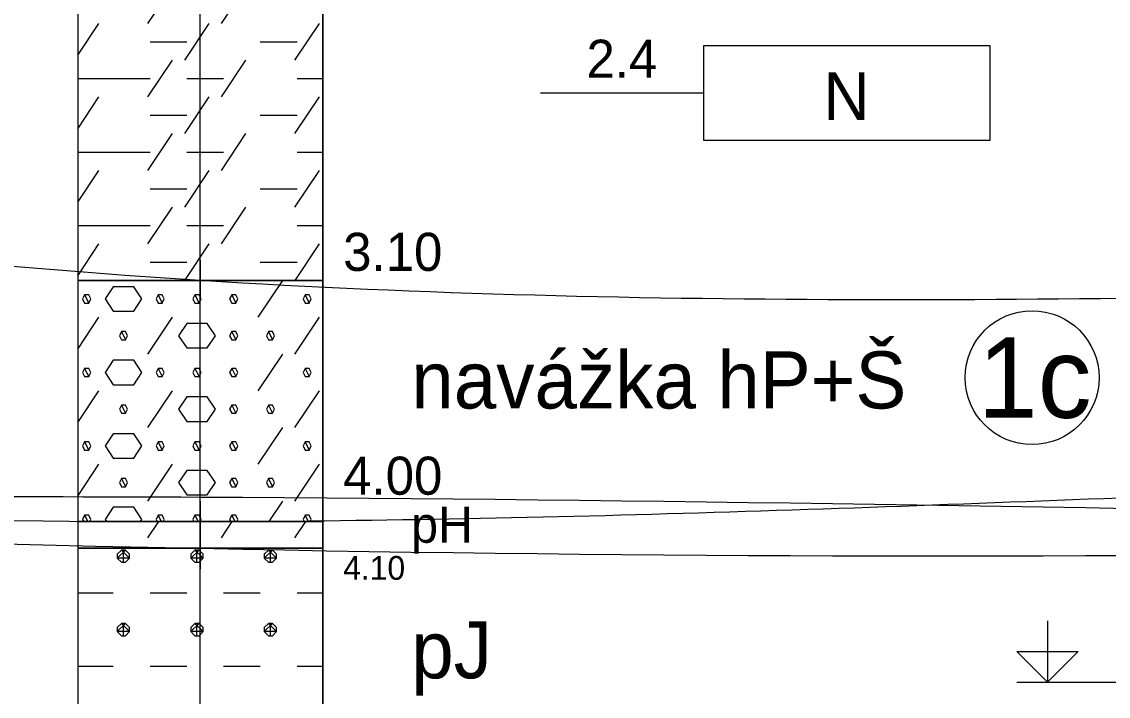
# Model space of a CAD drawing. Extents: x 3042 to 4120, y 576 to 2694.
# Drawn here: x 3328.17 to 3348.45, y 1428.2 to 1440.79 of the extents above; entities that cross this region are included whole.
import ezdxf

# ---------------------------------------------------------------- set-up
doc = ezdxf.new("R2010")
doc.units = 0
for name, color, linetype in [('18', 7, 'Continuous'), ('51', 7, 'Continuous'), ('52', 7, 'Continuous'), ('53', 7, 'Continuous'), ('56', 7, 'Continuous'), ('61', 7, 'Continuous'), ('62', 7, 'Continuous'), ('HPV', 7, 'Continuous'), ('rozhraní', 7, 'Continuous')]:
    doc.layers.add(name, color=color, linetype=linetype)

msp = doc.modelspace()

# ---------------------------------------------------------------- linework, layer by layer
at = {"layer": '18'}
msp.add_line((3331.502, 1401.464), (3331.502, 1451.464), dxfattribs=at)
at = {"layer": '51'}
for p, q in [((3330.526, 1440.762), (3330.984, 1441.448)), ((3331.898, 1440.762), (3332.355, 1441.448)), ((3329.216, 1440.168), (3329.612, 1440.762)), ((3331.212, 1440.076), (3331.669, 1440.762)), ((3333.27, 1440.076), (3333.727, 1440.762)), ((3330.565, 1440.419), (3331.25, 1440.419)), ((3332.622, 1440.419), (3333.308, 1440.419)), ((3330.526, 1439.39), (3330.984, 1440.076)), ((3331.898, 1439.39), (3332.355, 1440.076)), ((3329.216, 1439.733), (3329.879, 1439.733)), ((3329.879, 1439.733), (3330.565, 1439.733)), ((3331.25, 1439.733), (3331.936, 1439.733)), ((3333.308, 1439.733), (3333.788, 1439.733)), ((3329.216, 1438.796), (3329.612, 1439.39)), ((3331.212, 1438.705), (3331.669, 1439.39)), ((3333.27, 1438.705), (3333.727, 1439.39)), ((3330.565, 1439.048), (3331.25, 1439.048)), ((3332.622, 1439.048), (3333.308, 1439.048)), ((3330.526, 1438.019), (3330.984, 1438.705)), ((3331.898, 1438.019), (3332.355, 1438.705)), ((3329.216, 1438.362), (3329.879, 1438.362)), ((3329.879, 1438.362), (3330.565, 1438.362)), ((3331.25, 1438.362), (3331.936, 1438.362)), ((3333.308, 1438.362), (3333.788, 1438.362)), ((3329.216, 1437.424), (3329.612, 1438.019)), ((3331.212, 1437.333), (3331.669, 1438.019)), ((3333.27, 1437.333), (3333.727, 1438.019)), ((3330.565, 1437.676), (3331.25, 1437.676)), ((3332.622, 1437.676), (3333.308, 1437.676)), ((3330.526, 1436.647), (3330.984, 1437.333)), ((3331.898, 1436.647), (3332.355, 1437.333)), ((3329.216, 1436.99), (3329.879, 1436.99)), ((3329.879, 1436.99), (3330.565, 1436.99)), ((3331.25, 1436.99), (3331.936, 1436.99)), ((3333.308, 1436.99), (3333.788, 1436.99)), ((3329.216, 1436.053), (3329.612, 1436.647)), ((3331.214, 1435.964), (3331.669, 1436.647)), ((3333.271, 1435.964), (3333.727, 1436.647)), ((3330.565, 1436.304), (3331.25, 1436.304)), ((3332.622, 1436.304), (3333.308, 1436.304)), ((3330.526, 1435.961), (3330.528, 1435.964)), ((3332.584, 1435.276), (3333.041, 1435.961)), ((3333.27, 1435.961), (3333.271, 1435.964)), ((3329.216, 1434.681), (3329.612, 1435.276)), ((3330.526, 1434.59), (3330.984, 1435.276)), ((3333.27, 1434.59), (3333.727, 1435.276)), ((3332.584, 1433.904), (3333.041, 1434.59)), ((3329.216, 1433.31), (3329.612, 1433.904)), ((3330.526, 1433.218), (3330.984, 1433.904)), ((3333.27, 1433.218), (3333.727, 1433.904)), ((3332.584, 1432.532), (3333.041, 1433.218)), ((3329.216, 1431.938), (3329.612, 1432.532)), ((3330.526, 1431.847), (3330.984, 1432.532)), ((3333.27, 1431.847), (3333.727, 1432.532)), ((3332.786, 1431.464), (3333.041, 1431.847)), ((3330.526, 1431.161), (3330.728, 1431.464)), ((3331.898, 1431.161), (3332.1, 1431.464)), ((3333.27, 1431.161), (3333.472, 1431.464)), ((3330.069, 1430.704), (3330.069, 1430.932)), ((3331.441, 1430.704), (3331.441, 1430.932)), ((3332.812, 1430.704), (3332.812, 1430.932)), ((3329.216, 1430.132), (3329.879, 1430.132)), ((3330.565, 1430.132), (3331.25, 1430.132)), ((3331.936, 1430.132), (3332.622, 1430.132)), ((3333.308, 1430.132), (3333.788, 1430.132)), ((3330.069, 1429.332), (3330.069, 1429.561)), ((3331.441, 1429.332), (3331.441, 1429.561)), ((3332.812, 1429.332), (3332.812, 1429.561)), ((3329.216, 1428.761), (3329.879, 1428.761)), ((3330.565, 1428.761), (3331.25, 1428.761)), ((3331.936, 1428.761), (3332.622, 1428.761)), ((3333.308, 1428.761), (3333.788, 1428.761))]:
    msp.add_line(p, q, dxfattribs=at)
for points in [[(3329.216, 1435.964), (3333.788, 1435.964), (3333.788, 1445.464), (3329.216, 1445.464)], [(3329.216, 1431.464), (3333.788, 1431.464), (3333.788, 1435.964), (3329.216, 1435.964)], [(3329.216, 1430.964), (3333.788, 1430.964), (3333.788, 1431.464), (3329.216, 1431.464)], [(3329.216, 1427.464), (3333.788, 1427.464), (3333.788, 1430.964), (3329.216, 1430.964)]]:
    msp.add_lwpolyline(points, close=True, dxfattribs=at)
for points in [[(3329.879, 1435.39), (3330.26, 1435.39), (3330.412, 1435.619), (3330.26, 1435.847), (3329.879, 1435.847), (3329.726, 1435.619), (3329.879, 1435.39)], [(3329.345, 1435.695), (3329.307, 1435.619), (3329.345, 1435.542), (3329.422, 1435.542), (3329.46, 1435.619), (3329.422, 1435.695), (3329.345, 1435.695), (3329.422, 1435.542)], [(3330.717, 1435.695), (3330.679, 1435.619), (3330.717, 1435.542), (3330.793, 1435.542), (3330.831, 1435.619), (3330.793, 1435.695), (3330.717, 1435.695), (3330.793, 1435.542)], [(3331.403, 1435.695), (3331.365, 1435.619), (3331.403, 1435.542), (3331.479, 1435.542), (3331.517, 1435.619), (3331.479, 1435.695), (3331.403, 1435.695), (3331.479, 1435.542)], [(3332.089, 1435.695), (3332.05, 1435.619), (3332.089, 1435.542), (3332.165, 1435.542), (3332.203, 1435.619), (3332.165, 1435.695), (3332.089, 1435.695), (3332.165, 1435.542)], [(3333.46, 1435.695), (3333.422, 1435.619), (3333.46, 1435.542), (3333.536, 1435.542), (3333.574, 1435.619), (3333.536, 1435.695), (3333.46, 1435.695), (3333.536, 1435.542)], [(3331.25, 1434.704), (3331.631, 1434.704), (3331.784, 1434.933), (3331.631, 1435.161), (3331.25, 1435.161), (3331.098, 1434.933), (3331.25, 1434.704)], [(3330.031, 1435.009), (3329.993, 1434.933), (3330.031, 1434.857), (3330.107, 1434.857), (3330.145, 1434.933), (3330.107, 1435.009), (3330.031, 1435.009), (3330.107, 1434.857)], [(3332.089, 1435.009), (3332.05, 1434.933), (3332.089, 1434.857), (3332.165, 1434.857), (3332.203, 1434.933), (3332.165, 1435.009), (3332.089, 1435.009), (3332.165, 1434.857)], [(3332.774, 1435.009), (3332.736, 1434.933), (3332.774, 1434.857), (3332.851, 1434.857), (3332.889, 1434.933), (3332.851, 1435.009), (3332.774, 1435.009), (3332.851, 1434.857)], [(3329.879, 1434.018), (3330.26, 1434.018), (3330.412, 1434.247), (3330.26, 1434.476), (3329.879, 1434.476), (3329.726, 1434.247), (3329.879, 1434.018)], [(3329.345, 1434.323), (3329.307, 1434.247), (3329.345, 1434.171), (3329.422, 1434.171), (3329.46, 1434.247), (3329.422, 1434.323), (3329.345, 1434.323), (3329.422, 1434.171)], [(3330.717, 1434.323), (3330.679, 1434.247), (3330.717, 1434.171), (3330.793, 1434.171), (3330.831, 1434.247), (3330.793, 1434.323), (3330.717, 1434.323), (3330.793, 1434.171)], [(3331.403, 1434.323), (3331.365, 1434.247), (3331.403, 1434.171), (3331.479, 1434.171), (3331.517, 1434.247), (3331.479, 1434.323), (3331.403, 1434.323), (3331.479, 1434.171)], [(3332.089, 1434.323), (3332.05, 1434.247), (3332.089, 1434.171), (3332.165, 1434.171), (3332.203, 1434.247), (3332.165, 1434.323), (3332.089, 1434.323), (3332.165, 1434.171)], [(3333.46, 1434.323), (3333.422, 1434.247), (3333.46, 1434.171), (3333.536, 1434.171), (3333.574, 1434.247), (3333.536, 1434.323), (3333.46, 1434.323), (3333.536, 1434.171)], [(3330.031, 1433.637), (3329.993, 1433.561), (3330.031, 1433.485), (3330.107, 1433.485), (3330.145, 1433.561), (3330.107, 1433.637), (3330.031, 1433.637), (3330.107, 1433.485)], [(3331.25, 1433.333), (3331.631, 1433.333), (3331.784, 1433.561), (3331.631, 1433.79), (3331.25, 1433.79), (3331.098, 1433.561), (3331.25, 1433.333)], [(3332.089, 1433.637), (3332.05, 1433.561), (3332.089, 1433.485), (3332.165, 1433.485), (3332.203, 1433.561), (3332.165, 1433.637), (3332.089, 1433.637), (3332.165, 1433.485)], [(3332.774, 1433.637), (3332.736, 1433.561), (3332.774, 1433.485), (3332.851, 1433.485), (3332.889, 1433.561), (3332.851, 1433.637), (3332.774, 1433.637), (3332.851, 1433.485)], [(3329.879, 1432.647), (3330.26, 1432.647), (3330.412, 1432.875), (3330.26, 1433.104), (3329.879, 1433.104), (3329.726, 1432.875), (3329.879, 1432.647)], [(3329.345, 1432.952), (3329.307, 1432.875), (3329.345, 1432.799), (3329.422, 1432.799), (3329.46, 1432.875), (3329.422, 1432.952), (3329.345, 1432.952), (3329.422, 1432.799)], [(3330.717, 1432.952), (3330.679, 1432.875), (3330.717, 1432.799), (3330.793, 1432.799), (3330.831, 1432.875), (3330.793, 1432.952), (3330.717, 1432.952), (3330.793, 1432.799)], [(3331.403, 1432.952), (3331.365, 1432.875), (3331.403, 1432.799), (3331.479, 1432.799), (3331.517, 1432.875), (3331.479, 1432.952), (3331.403, 1432.952), (3331.479, 1432.799)], [(3332.089, 1432.952), (3332.05, 1432.875), (3332.089, 1432.799), (3332.165, 1432.799), (3332.203, 1432.875), (3332.165, 1432.952), (3332.089, 1432.952), (3332.165, 1432.799)], [(3333.46, 1432.952), (3333.422, 1432.875), (3333.46, 1432.799), (3333.536, 1432.799), (3333.574, 1432.875), (3333.536, 1432.952), (3333.46, 1432.952), (3333.536, 1432.799)], [(3331.25, 1431.961), (3331.631, 1431.961), (3331.784, 1432.19), (3331.631, 1432.418), (3331.25, 1432.418), (3331.098, 1432.19), (3331.25, 1431.961)], [(3330.031, 1432.266), (3329.993, 1432.19), (3330.031, 1432.113), (3330.107, 1432.113), (3330.145, 1432.19), (3330.107, 1432.266), (3330.031, 1432.266), (3330.107, 1432.113)], [(3332.089, 1432.266), (3332.05, 1432.19), (3332.089, 1432.113), (3332.165, 1432.113), (3332.203, 1432.19), (3332.165, 1432.266), (3332.089, 1432.266), (3332.165, 1432.113)], [(3332.774, 1432.266), (3332.736, 1432.19), (3332.774, 1432.113), (3332.851, 1432.113), (3332.889, 1432.19), (3332.851, 1432.266), (3332.774, 1432.266), (3332.851, 1432.113)], [(3329.345, 1431.58), (3329.307, 1431.504), (3329.327, 1431.464)], [(3329.44, 1431.464), (3329.46, 1431.504), (3329.422, 1431.58), (3329.345, 1431.58), (3329.403, 1431.464)], [(3330.386, 1431.464), (3330.412, 1431.504), (3330.26, 1431.732), (3329.879, 1431.732), (3329.726, 1431.504), (3329.753, 1431.464)], [(3330.717, 1431.58), (3330.679, 1431.504), (3330.699, 1431.464)], [(3330.811, 1431.464), (3330.831, 1431.504), (3330.793, 1431.58), (3330.717, 1431.58), (3330.775, 1431.464)], [(3331.403, 1431.58), (3331.365, 1431.504), (3331.385, 1431.464)], [(3331.497, 1431.464), (3331.517, 1431.504), (3331.479, 1431.58), (3331.403, 1431.58), (3331.461, 1431.464)], [(3332.089, 1431.58), (3332.05, 1431.504), (3332.07, 1431.464)], [(3332.183, 1431.464), (3332.203, 1431.504), (3332.165, 1431.58), (3332.089, 1431.58), (3332.147, 1431.464)], [(3333.46, 1431.58), (3333.422, 1431.504), (3333.442, 1431.464)], [(3333.554, 1431.464), (3333.574, 1431.504), (3333.536, 1431.58), (3333.46, 1431.58), (3333.518, 1431.464)], [(3330.031, 1430.932), (3329.955, 1430.856), (3329.955, 1430.78), (3330.031, 1430.704), (3330.107, 1430.704), (3330.184, 1430.78), (3330.184, 1430.856), (3330.107, 1430.932), (3330.031, 1430.932), (3330.184, 1430.78), (3329.955, 1430.78), (3330.107, 1430.932)], [(3331.403, 1430.932), (3331.327, 1430.856), (3331.327, 1430.78), (3331.403, 1430.704), (3331.479, 1430.704), (3331.555, 1430.78), (3331.555, 1430.856), (3331.479, 1430.932), (3331.403, 1430.932), (3331.555, 1430.78), (3331.327, 1430.78), (3331.479, 1430.932)], [(3332.774, 1430.932), (3332.698, 1430.856), (3332.698, 1430.78), (3332.774, 1430.704), (3332.851, 1430.704), (3332.927, 1430.78), (3332.927, 1430.856), (3332.851, 1430.932), (3332.774, 1430.932), (3332.927, 1430.78), (3332.698, 1430.78), (3332.851, 1430.932)], [(3330.031, 1429.561), (3329.955, 1429.484), (3329.955, 1429.408), (3330.031, 1429.332), (3330.107, 1429.332), (3330.184, 1429.408), (3330.184, 1429.484), (3330.107, 1429.561), (3330.031, 1429.561), (3330.184, 1429.408), (3329.955, 1429.408), (3330.107, 1429.561)], [(3331.403, 1429.561), (3331.327, 1429.484), (3331.327, 1429.408), (3331.403, 1429.332), (3331.479, 1429.332), (3331.555, 1429.408), (3331.555, 1429.484), (3331.479, 1429.561), (3331.403, 1429.561), (3331.555, 1429.408), (3331.327, 1429.408), (3331.479, 1429.561)], [(3332.774, 1429.561), (3332.698, 1429.484), (3332.698, 1429.408), (3332.774, 1429.332), (3332.851, 1429.332), (3332.927, 1429.408), (3332.927, 1429.484), (3332.851, 1429.561), (3332.774, 1429.561), (3332.927, 1429.408), (3332.698, 1429.408), (3332.851, 1429.561)]]:
    msp.add_lwpolyline(points, dxfattribs=at)
at = {"layer": '53'}
for p, q in [((3329.216, 1451.464), (3329.216, 1401.464)), ((3333.788, 1451.464), (3333.788, 1401.464)), ((3329.216, 1435.964), (3333.788, 1435.964)), ((3329.216, 1431.464), (3333.788, 1431.464)), ((3329.216, 1430.964), (3333.788, 1430.964))]:
    msp.add_line(p, q, dxfattribs=at)
at = {"layer": '56'}
for p, q in [((3331.502, 1436.345), (3331.502, 1435.583)), ((3331.121, 1435.964), (3331.883, 1435.964)), ((3331.502, 1431.845), (3331.502, 1431.083)), ((3331.121, 1431.464), (3331.883, 1431.464)), ((3331.502, 1431.345), (3331.502, 1430.583)), ((3331.121, 1430.964), (3331.883, 1430.964))]:
    msp.add_line(p, q, dxfattribs=at)
at = {"layer": '61'}
msp.add_line((3346.742, 1428.464), (3351.737, 1428.464), dxfattribs=at)
msp.add_lwpolyline([(3347.313, 1429.607), (3347.313, 1428.464), (3346.742, 1429.035), (3347.885, 1429.035), (3347.313, 1428.464)], dxfattribs=at)
at = {"layer": '62'}
msp.add_line((3337.852, 1439.464), (3340.9, 1439.464), dxfattribs=at)
msp.add_lwpolyline([(3346.234, 1438.575), (3340.9, 1438.575), (3340.9, 1440.353), (3346.234, 1440.353), (3346.234, 1438.575)], dxfattribs=at)
at = {"layer": 'HPV'}
msp.add_spline([(3456.273, 1433.82), (3381.832, 1431.271), (3331.502, 1431.914), (3319.823, 1431.914)], degree=3, dxfattribs=at)
at = {"layer": 'rozhraní'}
msp.add_circle((3347.024, 1434.15), 1.25, dxfattribs=at)
for points in [[(3356.525, 1435.755), (3331.502, 1435.964), (3301.662, 1439.299), (3286.47, 1440.682)], [(3260.637, 1433.124), (3269.032, 1433.064), (3331.502, 1430.964), (3381.832, 1431.714), (3448.222, 1434.864), (3457.804, 1434.864)], [(3260.628, 1434.017), (3269.032, 1434.064), (3331.497, 1431.464), (3350.107, 1431.964)], [(3261.496, 1419.657), (3269.032, 1420.064), (3276.869, 1420.657), (3284.683, 1421.527), (3300.27, 1423.734), (3315.855, 1425.956), (3323.667, 1426.844), (3331.502, 1427.464), (3344.075, 1427.667), (3356.665, 1427.215), (3369.255, 1426.701), (3381.832, 1426.714), (3398.427, 1427.714), (3415.014, 1429.102), (3431.607, 1430.333), (3448.222, 1430.864), (3456.64, 1430.864)]]:
    msp.add_spline(points, degree=3, dxfattribs=at)

# ---------------------------------------------------------------- texts
at = {"layer": '52'}
for s, height, p in [('3.10', 0.7112, (3334.169, 1436.143)), ('navážka hP+Š', 1.0668, (3335.439, 1433.574)), ('4.00', 0.7112, (3334.169, 1431.964)), ('pH', 0.6731, (3335.439, 1431.067)), ('4.10', 0.4445, (3334.169, 1430.376)), ('pJ', 1.0668, (3335.439, 1428.536))]:
    msp.add_text(s, height=height, dxfattribs=at).set_placement(p)
at = {"layer": '62'}
for s, height, p in [('2.4', 0.7112, (3338.709, 1439.748)), ('N', 0.889, (3343.133, 1438.962))]:
    msp.add_text(s, height=height, dxfattribs=at).set_placement(p)
at = {"layer": 'rozhraní'}
msp.add_text('1c', height=1.5, dxfattribs=at).set_placement((3346.014, 1433.4))

doc.saveas('drawing.dxf')
